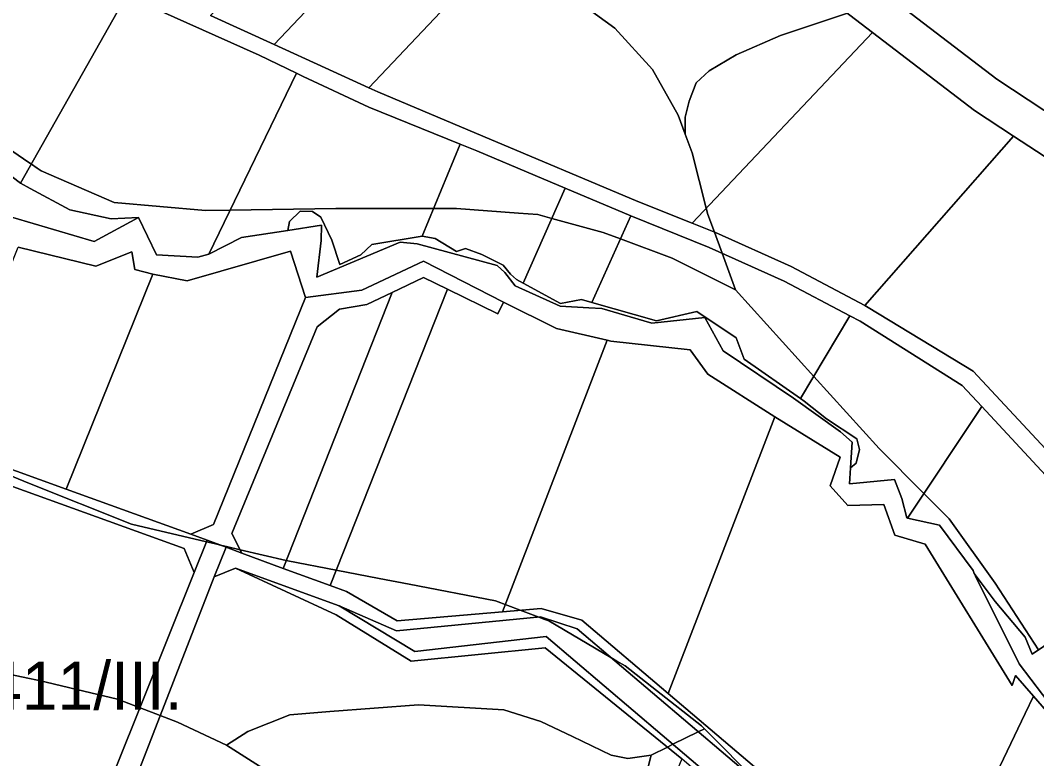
# Model space of a CAD drawing. Extents: x -522079 to -518792, y -1142400 to -1139961.
# Drawn here: x -520002.4 to -519685.2, y -1141142.6 to -1140912.1 of the extents above; entities that cross this region are included whole.
import ezdxf

# ---------------------------------------------------------------- set-up
doc = ezdxf.new("R2010")
doc.units = 0
for name, color, linetype in [('Hranice parcel', 7, 'Continuous'), ('Parcelní čísla', 7, 'Continuous'), ('Poz předměty', 7, 'Continuous'), ('Vnitřní kresba', 7, 'Continuous'), ('Značky bodu BP', 7, 'Continuous'), ('Značky budov', 7, 'Continuous'), ('Značky kultur', 7, 'Continuous')]:
    doc.layers.add(name, color=color, linetype=linetype)

msp = doc.modelspace()

# ---------------------------------------------------------------- linework, layer by layer
at = {"layer": 'Hranice parcel'}
for points in [[(-519758.42, -1140883.91), (-519697.68, -1140930.5), (-519678.04, -1140943.34)], [(-519670.91, -1140962.34), (-519692.38, -1140948.3), (-519704.63, -1140940.29), (-519736.43, -1140915.9), (-519768.72, -1140891.13)], [(-519661.22, -1141076.98), (-519702.3, -1141032.7), (-519708.41, -1141026.12), (-519740.29, -1141006.03), (-519743.47, -1141004.35), (-519764.04, -1140993.49), (-519787.36, -1140982.97), (-519811.83, -1140973.18), (-519832.3, -1140964.53), (-519841.67, -1140960.58), (-519859.94, -1140952.86), (-519865.12, -1140950.76), (-519893.61, -1140939.25), (-519914.16, -1140929.63), (-519916.21, -1140928.63), (-519927.83, -1140922.94), (-519959.29, -1140908.89)], [(-519943.08, -1140910.55), (-519923.13, -1140919.66), (-519907.29, -1140926.89), (-519893.61, -1140933.19), (-519890.83, -1140934.46), (-519858.03, -1140948.23), (-519809.71, -1140968.63), (-519792.75, -1140975.43), (-519785.4, -1140978.37), (-519761.84, -1140988.99), (-519738.84, -1141001.14), (-519737.76, -1141001.71), (-519704.97, -1141021.67), (-519678.16, -1141050.41)], [(-519679.71, -1141127.39), (-519690.7, -1141113), (-519704.33, -1141085.64), (-519704.67, -1141084.75), (-519702.87, -1141087.27), (-519698.11, -1141093.5), (-519688.8, -1141104.67), (-519686.59, -1141109.94), (-519660.92, -1141092.62)]]:
    msp.add_lwpolyline(points, dxfattribs=at)
for points in [[(-520079.53, -1141019.58), (-520170.88, -1140963.13), (-520175.23, -1140960.44), (-520178.74, -1140956.58), (-520181.77, -1140953.24), (-520180.26, -1140950.09), (-520156.19, -1140899.86), (-520151.68, -1140896.26), (-520149.94, -1140892.73), (-520146.75, -1140896.12), (-520154.18, -1140907.23), (-520173.77, -1140949.3), (-520172.97, -1140956.99), (-520147.43, -1140972.36), (-520125.63, -1140985.48), (-520084.54, -1141010.19), (-520030.55, -1141043.1), (-520027.48, -1141044.21), (-519988.12, -1141058.45), (-519949.16, -1141072.54), (-519944.08, -1141074.41), (-519948.1, -1141084.44), (-519951.21, -1141077.01), (-520032.33, -1141047.7)], [(-520002.28, -1140962.91), (-519999.3, -1140964.63), (-519986.94, -1140971.3), (-519974.08, -1140974.02), (-519965.47, -1140973.69), (-519979.37, -1140981.19), (-520011.16, -1140971.75), (-520017.69, -1140966.19), (-520051.93, -1140931.48), (-520046.33, -1140932.29), (-520029.76, -1140941.98), (-520015.17, -1140949.95), (-520009.84, -1140957.29)], [(-519918.88, -1140977.69), (-519918.38, -1140974.88), (-519915.05, -1140971.67), (-519911.23, -1140971.74), (-519908.61, -1140973.6), (-519905.17, -1140980.75), (-519902.71, -1140988.32), (-519896.08, -1140985.31), (-519892.69, -1140982.05), (-519876.99, -1140979.51), (-519872.87, -1140980.23), (-519866.25, -1140984.26), (-519863.48, -1140983.31), (-519858.36, -1140985.19), (-519853.77, -1140987.48), (-519851.69, -1140988.51), (-519849.37, -1140991.35), (-519847.55, -1140992.96), (-519845.46, -1140994.11), (-519833.76, -1141000.55), (-519827.26, -1140999.27), (-519824.03, -1141000.19), (-519803.83, -1141005.95), (-519791.3, -1141002.97), (-519778.94, -1141011.27), (-519776.47, -1141017.92), (-519758.88, -1141030.21), (-519757.71, -1141031.03), (-519750.8, -1141036.52), (-519741.29, -1141042.76), (-519740.45, -1141046.04), (-519741.49, -1141050.32), (-519743.3, -1141051.84), (-519742.77, -1141043.74), (-519746.47, -1141040.52), (-519761.05, -1141030.01), (-519783.07, -1141015.31), (-519788.8, -1141004.86), (-519805.33, -1141006.69), (-519812.07, -1141004.64), (-519820.93, -1141002.11), (-519825.01, -1141001.81), (-519833.92, -1141001.35), (-519847.96, -1140994.97), (-519851.21, -1140990.81), (-519853.55, -1140988.6), (-519878.53, -1140981.83), (-519883.85, -1140981.36), (-519909.8, -1140992.3), (-519908.53, -1140980.82), (-519908.41, -1140976.07)], [(-519980.55, -1141165.39), (-519948.1, -1141084.44), (-519944.08, -1141074.41), (-519938.17, -1141076.59), (-519941.9, -1141085.78), (-519973.57, -1141167.53), (-520007.53, -1141254.06), (-520004.78, -1141260.17), (-520020.92, -1141254.2), (-520014.17, -1141252.24)]]:
    msp.add_lwpolyline(points, close=True, dxfattribs=at)
at = {"layer": 'Parcelní čísla'}
for points in [[(-519758.42, -1140883.91), (-519698.98, -1140816.54), (-519677.02, -1140829.78), (-519655.55, -1140840.89), (-519633.63, -1140850.83), (-519613.39, -1140860.38), (-519678.04, -1140943.34), (-519697.68, -1140930.5)], [(-519865.19, -1140832.11), (-519845.71, -1140837.84), (-519923.13, -1140919.66), (-519943.08, -1140910.55)], [(-519923.13, -1140919.66), (-519845.71, -1140837.84), (-519829.78, -1140842.53), (-519815.37, -1140850.5), (-519893.61, -1140933.19), (-519907.29, -1140926.89)], [(-519815.37, -1140850.5), (-519797.7, -1140860.26), (-519768.72, -1140891.13), (-519736.43, -1140915.9), (-519792.75, -1140975.43), (-519809.71, -1140968.63), (-519858.03, -1140948.23), (-519890.83, -1140934.46), (-519893.61, -1140933.19)], [(-519792.75, -1140975.43), (-519736.43, -1140915.9), (-519704.63, -1140940.29), (-519692.38, -1140948.3), (-519738.84, -1141001.14), (-519761.84, -1140988.99), (-519785.4, -1140978.37)], [(-519692.38, -1140948.3), (-519670.91, -1140962.34), (-519655.67, -1140987.81), (-519639.1, -1141009.23), (-519678.16, -1141050.41), (-519704.97, -1141021.67), (-519737.76, -1141001.71), (-519738.84, -1141001.14)], [(-520079.53, -1141019.58), (-520032.33, -1141047.7), (-519951.21, -1141077.01), (-519948.1, -1141084.44), (-519980.55, -1141165.39), (-520014.17, -1141252.24), (-520020.92, -1141254.2), (-520158.56, -1141206.98), (-520129.38, -1141144.09)], [(-519935.26, -1141083.16), (-519941.9, -1141085.78), (-519938.17, -1141076.59), (-519933.25, -1141078.41), (-519920.33, -1141083.18), (-519905.71, -1141088.58), (-519900.64, -1141090.45), (-519884.82, -1141099.57), (-519851.93, -1141096.73), (-519839.81, -1141095.68), (-519827.19, -1141099.4), (-519800.19, -1141122.28), (-519756.03, -1141159.77), (-519721.93, -1141194.85), (-519723.28, -1141198.33), (-519758.08, -1141162.05), (-519828.65, -1141102.04), (-519840, -1141098.37), (-519884.97, -1141102.71), (-519902.89, -1141094.84)], [(-519864.09, -1141309.46), (-519903.26, -1141295.46), (-520004.78, -1141260.17), (-520007.53, -1141254.06), (-519973.57, -1141167.53), (-519941.9, -1141085.78), (-519935.26, -1141083.16), (-519903.85, -1141097.73), (-519880.39, -1141112.19), (-519838.58, -1141107.96), (-519795.94, -1141142.67), (-519845.38, -1141262.74)], [(-519935.26, -1141083.16), (-519902.89, -1141094.84), (-519879.3, -1141109.16), (-519838.27, -1141104.49), (-519765.82, -1141166.07), (-519746.23, -1141205.14), (-519728.39, -1141213.65), (-519728.58, -1141216.84), (-519747.5, -1141207.73), (-519766.69, -1141167.92), (-519795.94, -1141142.67), (-519838.58, -1141107.96), (-519880.39, -1141112.19), (-519903.85, -1141097.73)], [(-519728.23, -1141211.06), (-519728.39, -1141213.65), (-519746.23, -1141205.14), (-519765.82, -1141166.07), (-519838.27, -1141104.49), (-519879.3, -1141109.16), (-519902.89, -1141094.84), (-519884.97, -1141102.71), (-519840, -1141098.37), (-519828.65, -1141102.04), (-519758.08, -1141162.05), (-519723.28, -1141198.33)]]:
    msp.add_lwpolyline(points, close=True, dxfattribs=at)
at = {"layer": 'Poz předměty'}
for points in [[(-520022.73, -1140882.19), (-519999.48, -1140892), (-519969.45, -1140904.62), (-520002.28, -1140962.91), (-520009.84, -1140957.29), (-520015.17, -1140949.95), (-520029.76, -1140941.98), (-520046.33, -1140932.29), (-520051.93, -1140931.48), (-520055.67, -1140929.56)], [(-519969.45, -1140904.62), (-519959.29, -1140908.89), (-519927.83, -1140922.94), (-519916.21, -1140928.63), (-519943.51, -1140985.08), (-519947.03, -1140986.05), (-519959.93, -1140985.31), (-519965.47, -1140973.69), (-519974.08, -1140974.02), (-519986.94, -1140971.3), (-519999.3, -1140964.63), (-520002.28, -1140962.91)], [(-519832.3, -1140964.53), (-519845.46, -1140994.11), (-519847.55, -1140992.96), (-519849.37, -1140991.35), (-519851.69, -1140988.51), (-519853.77, -1140987.48), (-519858.36, -1140985.19), (-519863.48, -1140983.31), (-519866.25, -1140984.26), (-519872.87, -1140980.23), (-519876.99, -1140979.51), (-519865.12, -1140950.76), (-519859.94, -1140952.86), (-519841.67, -1140960.58)], [(-520003.11, -1140982.94), (-519978.85, -1140988.86), (-519967.54, -1140984.38), (-519966.67, -1140989.91), (-519961.08, -1140991.39), (-519988.12, -1141058.45), (-520027.48, -1141044.21)], [(-519949.16, -1141072.54), (-519988.12, -1141058.45), (-519961.08, -1140991.39), (-519950.36, -1140993.42), (-519918.04, -1140984.12), (-519913.39, -1140998.68), (-519942.1, -1141069.48)], [(-519909.75, -1141007.77), (-519936.42, -1141072.28), (-519933.25, -1141078.41), (-519938.17, -1141076.59), (-519944.08, -1141074.41), (-519949.16, -1141072.54), (-519942.1, -1141069.48), (-519913.39, -1140998.68), (-519895.77, -1140996.31), (-519876.6, -1140987.29), (-519851.59, -1141000.07), (-519853.31, -1141003.69), (-519869.05, -1140996), (-519876.54, -1140992.34), (-519886.37, -1140997.05), (-519894.21, -1141000.8), (-519902.79, -1141002.3)], [(-519905.71, -1141088.58), (-519920.33, -1141083.18), (-519886.37, -1140997.05), (-519876.54, -1140992.34), (-519869.05, -1140996)], [(-519936.42, -1141072.28), (-519909.75, -1141007.77), (-519902.79, -1141002.3), (-519894.21, -1141000.8), (-519886.37, -1140997.05), (-519920.33, -1141083.18), (-519933.25, -1141078.41)], [(-519819.26, -1141011.99), (-519851.93, -1141096.73), (-519884.82, -1141099.57), (-519900.64, -1141090.45), (-519905.71, -1141088.58), (-519869.05, -1140996), (-519853.31, -1141003.69), (-519851.59, -1141000.07), (-519835.08, -1141008.27)], [(-519851.93, -1141096.73), (-519819.26, -1141011.99), (-519818.09, -1141012.26), (-519793.36, -1141014.98), (-519787.79, -1141022.58), (-519766.87, -1141035.85), (-519800.19, -1141122.28), (-519827.19, -1141099.4), (-519839.81, -1141095.68)], [(-519746.51, -1141048.43), (-519749.67, -1141057.47), (-519744.08, -1141063.56), (-519732.93, -1141063.24), (-519729.51, -1141072.8), (-519719.95, -1141075.61), (-519692.8, -1141119.72), (-519691.83, -1141116.63), (-519686.19, -1141123.12), (-519688.75, -1141128.51), (-519728.23, -1141211.06), (-519723.28, -1141198.33), (-519721.93, -1141194.85), (-519756.03, -1141159.77), (-519800.19, -1141122.28), (-519766.87, -1141035.85)]]:
    msp.add_lwpolyline(points, close=True, dxfattribs=at)
at = {"layer": 'Vnitřní kresba'}
for points in [[(-520011.16, -1140971.75), (-519979.37, -1140981.19), (-519965.47, -1140973.69), (-519959.93, -1140985.31), (-519947.03, -1140986.05), (-519943.51, -1140985.08), (-519933.4, -1140979.93), (-519918.88, -1140977.69), (-519908.41, -1140976.07), (-519908.53, -1140980.82), (-519909.8, -1140992.3), (-519883.85, -1140981.36), (-519878.53, -1140981.83), (-519853.55, -1140988.6), (-519851.21, -1140990.81), (-519847.96, -1140994.97), (-519833.92, -1141001.35), (-519825.01, -1141001.81), (-519820.93, -1141002.11), (-519812.07, -1141004.64), (-519805.33, -1141006.69), (-519788.8, -1141004.86), (-519783.07, -1141015.31), (-519761.05, -1141030.01), (-519746.47, -1141040.52), (-519742.77, -1141043.74), (-519743.3, -1141051.84), (-519743.63, -1141056.81), (-519729.57, -1141055.46), (-519727.24, -1141061.4), (-519725.71, -1141067.43), (-519725.48, -1141067.48), (-519715.52, -1141069.7), (-519705.02, -1141083.87), (-519704.67, -1141084.75), (-519704.33, -1141085.64), (-519690.7, -1141113), (-519679.71, -1141127.39)], [(-519676.06, -1141134.77), (-519686.19, -1141123.12), (-519691.83, -1141116.63), (-519692.8, -1141119.72), (-519719.95, -1141075.61), (-519729.51, -1141072.8), (-519732.93, -1141063.24), (-519744.08, -1141063.56), (-519749.67, -1141057.47), (-519746.51, -1141048.43), (-519766.87, -1141035.85), (-519787.79, -1141022.58), (-519793.36, -1141014.98), (-519818.09, -1141012.26), (-519819.26, -1141011.99), (-519835.08, -1141008.27), (-519851.59, -1141000.07), (-519876.6, -1140987.29), (-519895.77, -1140996.31), (-519913.39, -1140998.68), (-519918.04, -1140984.12), (-519950.36, -1140993.42), (-519961.08, -1140991.39), (-519966.67, -1140989.91), (-519967.54, -1140984.38), (-519978.85, -1140988.86), (-520003.11, -1140982.94)]]:
    msp.add_lwpolyline(points, dxfattribs=at)
at = {"layer": 'Značky bodu BP'}
for points in [[(-519837.21, -1140899.63), (-519816.83, -1140914.5), (-519805.1, -1140927.5), (-519797.07, -1140941.75), (-519794.89, -1140947.68), (-519792.75, -1140953.52), (-519788.32, -1140970.74), (-519787.81, -1140972.72), (-519785.79, -1140978.21), (-519783.39, -1140984.76), (-519783.36, -1140984.84), (-519779.16, -1140996.26), (-519798.92, -1140986.35), (-519815.06, -1140980.33), (-519820.53, -1140978.29), (-519836.48, -1140973.93), (-519840.91, -1140972.72), (-519846.93, -1140972.27), (-519866.23, -1140970.86), (-519873.42, -1140970.86), (-519903.89, -1140970.86), (-519936.88, -1140971.36), (-519944.64, -1140971.48), (-519973.05, -1140969), (-519995.89, -1140959.09), (-519997.09, -1140958.27), (-519998.95, -1140956.99), (-520000, -1140956.26), (-520027.38, -1140937.41)], [(-519744.27, -1140909.88), (-519765.19, -1140916.87), (-519778.96, -1140922.84), (-519787.42, -1140927.87), (-519791.49, -1140931.64), (-519793.68, -1140937.29), (-519794.93, -1140942.32), (-519794.89, -1140947.68), (-519797.07, -1140941.75), (-519805.1, -1140927.5), (-519816.83, -1140914.5), (-519837.21, -1140899.63)], [(-519684.63, -1141108.61), (-519698.14, -1141087.76), (-519712.47, -1141067.71), (-519720.36, -1141059.8), (-519734.35, -1141045.77), (-519754.73, -1141023.25), (-519779.16, -1140996.26), (-519783.36, -1140984.84), (-519783.39, -1140984.76), (-519785.79, -1140978.21), (-519787.81, -1140972.72), (-519788.32, -1140970.74), (-519792.75, -1140953.52), (-519794.89, -1140947.68), (-519794.93, -1140942.32), (-519793.68, -1140937.29), (-519791.49, -1140931.64), (-519787.42, -1140927.87), (-519778.96, -1140922.84), (-519765.19, -1140916.87), (-519744.27, -1140909.88)], [(-520027.38, -1140937.41), (-520000, -1140956.26), (-519998.95, -1140956.99), (-519997.09, -1140958.27), (-519995.89, -1140959.09), (-519973.05, -1140969), (-519944.64, -1140971.48), (-519936.88, -1140971.36), (-519903.89, -1140970.86), (-519873.42, -1140970.86), (-519866.23, -1140970.86), (-519846.93, -1140972.27), (-519840.91, -1140972.72), (-519836.48, -1140973.93), (-519820.53, -1140978.29), (-519815.06, -1140980.33), (-519798.92, -1140986.35), (-519779.16, -1140996.26), (-519754.73, -1141023.25), (-519734.35, -1141045.77), (-519720.36, -1141059.8), (-519712.47, -1141067.71), (-519698.14, -1141087.76), (-519684.63, -1141108.61)], [(-520011.71, -1141051.75), (-520000, -1141056.45), (-519967.65, -1141069.43), (-519944.28, -1141074.92), (-519941.48, -1141075.57), (-519939.95, -1141075.93), (-519938.08, -1141076.37), (-519933.78, -1141077.38), (-519919.38, -1141080.76), (-519918.91, -1141080.87), (-519903.81, -1141083.77), (-519890.42, -1141086.35), (-519881.05, -1141088.16), (-519854.09, -1141093.36), (-519846.4, -1141096.25), (-519840.61, -1141098.43), (-519839.05, -1141099.01), (-519837.49, -1141099.6), (-519818.07, -1141111.03), (-519816.18, -1141112.15), (-519813.64, -1141113.65), (-519803.89, -1141121.3), (-519789.78, -1141132.37), (-519788.91, -1141133.25), (-519790.83, -1141134.2), (-519798.71, -1141138.11), (-519800.46, -1141138.99), (-519805.48, -1141141.48), (-519812.79, -1141142.53), (-519818.02, -1141141.48), (-519830.03, -1141135.72), (-519839.95, -1141131), (-519851.44, -1141127.34), (-519878.08, -1141125.76), (-519905.77, -1141127.86), (-519918.3, -1141128.91), (-519931.36, -1141134.15), (-519938.01, -1141138.42), (-519953.38, -1141131.2), (-519958.7, -1141129.14), (-519965.03, -1141126.69), (-519972.04, -1141123.98), (-519984.76, -1141120.97), (-519994.29, -1141118.72), (-519996.98, -1141118.14), (-520000, -1141117.5), (-520014.8, -1141114.31)], [(-519772.01, -1141150.2), (-519788.91, -1141133.25), (-519789.78, -1141132.37), (-519803.89, -1141121.3), (-519813.64, -1141113.65), (-519816.18, -1141112.15), (-519818.07, -1141111.03), (-519837.49, -1141099.6), (-519839.05, -1141099.01), (-519840.61, -1141098.43), (-519846.4, -1141096.25), (-519854.09, -1141093.36), (-519881.05, -1141088.16), (-519890.42, -1141086.35), (-519903.81, -1141083.77), (-519918.91, -1141080.87), (-519919.38, -1141080.76), (-519933.78, -1141077.38), (-519938.08, -1141076.37), (-519939.95, -1141075.93), (-519941.48, -1141075.57), (-519944.28, -1141074.92), (-519967.65, -1141069.43), (-520000, -1141056.45), (-520011.71, -1141051.75)], [(-520014.8, -1141114.31), (-520000, -1141117.5), (-519996.98, -1141118.14), (-519994.29, -1141118.72), (-519984.76, -1141120.97), (-519972.04, -1141123.98), (-519965.03, -1141126.69), (-519958.7, -1141129.14), (-519953.38, -1141131.2), (-519938.01, -1141138.42), (-519926.55, -1141145.64)], [(-519926.55, -1141145.64), (-519938.01, -1141138.42), (-519931.36, -1141134.15), (-519918.3, -1141128.91), (-519905.77, -1141127.86), (-519878.08, -1141125.76), (-519851.44, -1141127.34), (-519839.95, -1141131), (-519830.03, -1141135.72), (-519818.02, -1141141.48), (-519812.79, -1141142.53), (-519805.48, -1141141.48), (-519809.14, -1141155.63)], [(-519809.14, -1141155.63), (-519805.48, -1141141.48), (-519800.46, -1141138.99), (-519798.71, -1141138.11), (-519790.83, -1141134.2), (-519788.91, -1141133.25), (-519772.01, -1141150.2)]]:
    msp.add_lwpolyline(points, dxfattribs=at)
at = {"layer": 'Značky budov'}
msp.add_lwpolyline([(-519687.67, -1141218.86), (-519709.65, -1141256.63), (-519720.8, -1141249.93), (-519714.2, -1141233.06), (-519705.26, -1141212.3), (-519728.23, -1141211.06), (-519688.75, -1141128.51), (-519686.19, -1141123.12), (-519676.06, -1141134.77), (-519667.13, -1141153.28), (-519663.19, -1141164.28), (-519654.81, -1141169.94)], close=True, dxfattribs=at)
at = {"layer": 'Značky kultur'}
for points in [[(-519943.51, -1140985.08), (-519916.21, -1140928.63), (-519914.16, -1140929.63), (-519893.61, -1140939.25), (-519865.12, -1140950.76), (-519876.99, -1140979.51), (-519892.69, -1140982.05), (-519896.08, -1140985.31), (-519902.71, -1140988.32), (-519905.17, -1140980.75), (-519908.61, -1140973.6), (-519911.23, -1140971.74), (-519915.05, -1140971.67), (-519918.38, -1140974.88), (-519918.88, -1140977.69), (-519933.4, -1140979.93)], [(-519845.46, -1140994.11), (-519832.3, -1140964.53), (-519811.83, -1140973.18), (-519824.03, -1141000.19), (-519827.26, -1140999.27), (-519833.76, -1141000.55)], [(-519824.03, -1141000.19), (-519811.83, -1140973.18), (-519787.36, -1140982.97), (-519764.04, -1140993.49), (-519743.47, -1141004.35), (-519758.88, -1141030.21), (-519776.47, -1141017.92), (-519778.94, -1141011.27), (-519791.3, -1141002.97), (-519803.83, -1141005.95)], [(-519743.47, -1141004.35), (-519740.29, -1141006.03), (-519708.41, -1141026.12), (-519702.3, -1141032.7), (-519725.48, -1141067.48), (-519725.71, -1141067.43), (-519727.24, -1141061.4), (-519729.57, -1141055.46), (-519743.63, -1141056.81), (-519743.3, -1141051.84), (-519741.49, -1141050.32), (-519740.45, -1141046.04), (-519741.29, -1141042.76), (-519750.8, -1141036.52), (-519757.71, -1141031.03), (-519758.88, -1141030.21)], [(-519702.3, -1141032.7), (-519661.22, -1141076.98), (-519659.49, -1141085.69), (-519660.92, -1141092.62), (-519686.59, -1141109.94), (-519688.8, -1141104.67), (-519698.11, -1141093.5), (-519702.87, -1141087.27), (-519704.67, -1141084.75), (-519705.02, -1141083.87), (-519715.52, -1141069.7), (-519725.48, -1141067.48)]]:
    msp.add_lwpolyline(points, close=True, dxfattribs=at)

# ---------------------------------------------------------------- texts
at = {"layer": 'Značky bodu BP'}
msp.add_text('62411/III.', height=15, rotation=0, dxfattribs=at).set_placement((-520035.39, -1141127.33))

doc.saveas('drawing.dxf')
